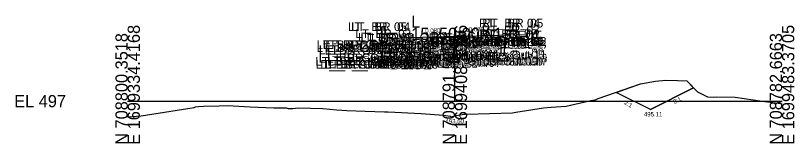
# Model space of a CAD drawing. Extents: x -63 to 1153, y -24 to 9522.
# Drawn here: x -25.7 to 152.8, y 6490.3 to 6519.6 of the extents above; entities that cross this region are included whole.
import ezdxf

# ---------------------------------------------------------------- set-up
doc = ezdxf.new("R2010")
doc.units = 0
for name, color, linetype in [('Default', 7, 'Continuous'), ('Exist Cross Section Cell', 7, 'Continuous'), ('Exist XS Center Line Elevation Label', 7, 'Continuous'), ('Exist XS Ground Line', 7, 'Continuous'), ('Prop CMT Concrete Structures', 7, 'Continuous'), ('Prop CMT DNC', 7, 'Continuous'), ('Prop CMT Slope Grass', 7, 'Continuous'), ('Prop XS DDE Earthwork Shape', 7, 'Continuous'), ('Prop XS Ditch Standard Text', 7, 'Continuous'), ('Prop XS SE Text', 7, 'Continuous'), ('Prop XS Side Slope Text', 7, 'Continuous')]:
    doc.layers.add(name, color=color, linetype=linetype)

msp = doc.modelspace()

# ---------------------------------------------------------------- linework, layer by layer
at = {"layer": 'Exist Cross Section Cell'}
for p, q in [((75, 6500), (75, 6516.82)), ((0, 6500), (75, 6500)), ((75, 6500), (150, 6500))]:
    msp.add_line(p, q, dxfattribs=at)
at = {"layer": 'Exist XS Ground Line'}
msp.add_lwpolyline([(0, 6496.43), (3.08, 6496.65), (15.21, 6498.56), (15.58, 6498.72), (16.25, 6498.8), (17.36, 6498.84), (20.94, 6498.96), (22.89, 6498.97), (28.09, 6498.68), (33.49, 6498.49), (36.36, 6498.44), (36.76, 6498.34), (37.14, 6498.31), (37.56, 6498.31), (37.88, 6498.34), (39.09, 6498.44), (44.77, 6498.3), (47.95, 6497.99), (50.26, 6497.85), (54.47, 6497.68), (58.91, 6497.54), (59.26, 6497.55), (59.68, 6497.55), (67.29, 6497.2), (72.37, 6496.81), (74.03, 6496.54), (74.22, 6496.44), (75, 6496.6), (77.05, 6497.02), (77.36, 6497.05), (77.65, 6497.04), (88.23, 6497.32), (88.99, 6497.48), (95.31, 6498.49), (97.05, 6498.64), (100.48, 6498.86), (106.14, 6500.13), (107.09, 6500.27), (107.22, 6500.32), (107.82, 6500.57), (117.56, 6503.95), (121.02, 6504.55), (123.34, 6504.8), (126.05, 6504.72), (128.18, 6504.62), (130.6, 6502.1), (132.88, 6500.98), (134.19, 6500.92), (134.98, 6500.96), (139.26, 6500.88), (145.48, 6499.97), (149.76, 6499.46), (150, 6499.42)], dxfattribs=at)
at = {"layer": 'Prop CMT Concrete Structures'}
for points in [[(75, 6514.85), (65.04, 6514.55), (59.75, 6514.39), (59.74, 6514.64), (59.16, 6515.48), (58.99, 6517.06), (58.25, 6517.06), (58.25, 6512.85)], [(75, 6514.85), (85, 6515.15), (87.59, 6515.23), (87.6, 6515.48), (88.18, 6516.31), (88.35, 6517.89), (89.09, 6517.89), (89.09, 6513.77)], [(75, 6513.35), (75, 6514.85)], [(75, 6513.35), (75, 6514.85)], [(58.25, 6512.85), (65.04, 6513.05), (75, 6513.35)], [(62.21, 6512.97), (61.37, 6512.94), (60.54, 6512.92)], [(60.54, 6512.92), (60.54, 6512.27)], [(62.21, 6512.27), (62.21, 6512.97)], [(75, 6513.35), (74.17, 6513.33)], [(74.17, 6513.33), (74.17, 6512.68)], [(89.09, 6513.77), (85, 6513.65), (75, 6513.35)], [(75, 6513.35), (75.83, 6513.38)], [(75, 6508.85), (75, 6513.35)], [(75, 6508.85), (75, 6513.35)], [(75.83, 6513.38), (75.83, 6512.68)], [(85.13, 6513.65), (85.97, 6513.68), (86.8, 6513.7)], [(85.13, 6513.01), (85.13, 6513.65)], [(85.63, 6512.51), (85.13, 6513.01)], [(86.8, 6513.01), (86.3, 6512.51)], [(86.8, 6513.7), (86.8, 6513.01)], [(60.54, 6512.27), (61.04, 6511.77)], [(61.04, 6511.77), (61.04, 6509.86)], [(61.71, 6511.77), (62.21, 6512.27)], [(61.71, 6509.86), (61.71, 6511.77)], [(74.17, 6512.68), (74.67, 6512.18)], [(74.67, 6512.18), (74.67, 6510.27)], [(75.83, 6512.68), (75.33, 6512.18)], [(75.33, 6512.18), (75.33, 6510.27)], [(85.63, 6510.6), (85.63, 6512.51)], [(86.3, 6512.51), (86.3, 6510.6)], [(61.04, 6509.86), (60.29, 6509.11)], [(62.46, 6509.11), (61.71, 6509.86)], [(74.67, 6510.27), (73.92, 6509.52)], [(73.92, 6509.52), (73.92, 6508.85)], [(75.33, 6510.27), (76.08, 6509.52)], [(76.08, 6509.52), (76.08, 6508.85)], [(84.88, 6509.85), (85.63, 6510.6)], [(84.88, 6509.18), (84.88, 6509.85)], [(86.3, 6510.6), (87.05, 6509.85)], [(87.05, 6509.85), (87.05, 6509.18)], [(60.29, 6509.11), (60.29, 6508.44)], [(60.29, 6508.44), (61.37, 6508.44), (62.46, 6508.44)], [(62.46, 6508.44), (62.46, 6509.11)], [(73.92, 6508.85), (75, 6508.85)], [(76.08, 6508.85), (75, 6508.85)], [(87.05, 6509.18), (85.97, 6509.18), (84.88, 6509.18)]]:
    msp.add_lwpolyline(points, dxfattribs=at)
at = {"layer": 'Prop CMT Slope Grass'}
for q in [(129.69, 6503.04), (112, 6502.02)]:
    msp.add_line((119.83, 6498.11), q, dxfattribs=at)
at = {"layer": 'Prop XS DDE Earthwork Shape'}
msp.add_lwpolyline([(112, 6502.02), (117.56, 6503.95), (121.02, 6504.55), (123.34, 6504.8), (126.05, 6504.72), (128.18, 6504.62), (129.69, 6503.04), (119.83, 6498.11)], close=True, dxfattribs=at)

# ---------------------------------------------------------------- texts
at = {"layer": 'Default'}
msp.add_text('-', height=0.0001, dxfattribs=at).set_placement((0, 6500))
at = {"layer": 'Exist Cross Section Cell'}
for s, p in [('L', (65, 6516.82)), ('15+50.00 / 1', (65, 6514.02)), ('EL 497', (-26, 6498.6))]:
    msp.add_text(s, height=2.8, dxfattribs=at).set_placement(p)
for s, p in [('E 1699334.4168', (2.8, 6490)), ('E 1699408.8936', (77.8, 6490)), ('E 1699483.3705', (152.8, 6490)), ('N 708800.3518', (0, 6490)), ('N 708791.5091', (75, 6490)), ('N 708782.6663', (150, 6490))]:
    msp.add_text(s, height=2.8, rotation=90, dxfattribs=at).set_placement(p)
at = {"layer": 'Exist XS Center Line Elevation Label'}
msp.add_text('493.60', height=1, dxfattribs=at).set_placement((72.85, 6494.89))
at = {"layer": 'Prop CMT DNC'}
for s, p in [('RT_ BR_04', (80.54, 6516.89)), ('RT_ BR_05', (81.28, 6516.89)), ('LT_ BR_05', (50.49, 6516.06)), ('LT_ BR_04', (51.23, 6516.06)), ('LT_BR_03', (52.21, 6514.48)), ('RT_BR_02', (80.61, 6514.48)), ('RT_BR_03', (81.19, 6515.31)), ('LT_BR_02', (52.8, 6513.64)), ('LT_BR_01', (53.37, 6513.39)), ('LT_PV1_OEOT', (55.78, 6513.55)), ('RT_BR_Girder Out 14', (68.52, 6512.65)), ('RT_BR_Girder Out 01', (69.27, 6512.68)), ('PV1_PGL', (69.47, 6513.85)), ('RT_BR_Girder Out 02', (69.54, 6512.7)), ('RT_PV1_OEOT', (75.69, 6514.15)), ('RT_BR_07', (78.01, 6512.65)), ('RT_BR_01', (81.17, 6514.23)), ('RT_BR_06', (82.05, 6512.77)), ('LT_BR_Girder Out 02', (43.33, 6511.92)), ('LT_BR_Girder Out 03', (43.33, 6511.27)), ('LT_BR_Girder Out 04', (43.83, 6510.77)), ('LT_BR_Girder Out 01', (44.73, 6511.94)), ('LT_BR_Girder Out 12', (45.14, 6510.77)), ('LT_BR_Girder Out 14', (45.64, 6511.97)), ('LT_BR_Girder Out 13', (45.64, 6511.27)), ('LT_BR_06', (51.26, 6511.85)), ('LT_BR_Girder Mid 02', (57.35, 6512.33)), ('LT_BR_Girder Mid 03', (57.35, 6511.68)), ('LT_BR_Girder Mid 04', (57.85, 6511.18)), ('LT_BR_07', (58.09, 6512.05)), ('RT_BR_Girder Mid 04', (58.47, 6511.18)), ('RT_BR_Girder Mid 02', (58.97, 6512.38)), ('RT_BR_Girder Mid 03', (58.97, 6511.68)), ('RT_BR_Girder Out 13', (68.52, 6512.01)), ('RT_BR_Girder Out 12', (69.02, 6511.51)), ('RT_BR_Girder Out 04', (69.04, 6511.51)), ('RT_BR_Girder Out 03', (69.54, 6512.01)), ('BR_PGL', (69.83, 6512.35)), ('LT_BR_Girder Mid 05', (57.85, 6509.27)), ('RT_BR_Girder Mid 05', (58.47, 6509.27)), ('RT_BR_Girder Out 05', (69.04, 6509.6)), ('RT_BR_Girder Out 11', (69.59, 6509.6)), ('LT_BR_Girder Out 06', (43.03, 6508.11)), ('LT_BR_Girder Out 07', (43.08, 6507.44)), ('LT_BR_Girder Out 05', (43.83, 6508.86)), ('LT_BR_Girder Out 08', (44.16, 6507.44)), ('LT_BR_Girder Out 09', (45.25, 6507.44)), ('LT_BR_Girder Out 11', (45.71, 6508.86)), ('LT_BR_Girder Out 10', (45.81, 6508.11)), ('LT_BR_Girder Mid 06', (57.05, 6508.52)), ('LT_BR_Girder Mid 07', (57.1, 6507.85)), ('RT_BR_Girder Mid 06', (59.17, 6508.52)), ('RT_BR_Girder Mid 07', (59.22, 6507.85)), ('BR_Girder Mid 08', (60.87, 6507.85)), ('RT_BR_Girder Out 09', (67.62, 6508.18)), ('RT_BR_Girder Out 10', (68.19, 6508.85)), ('RT_BR_Girder Out 08', (68.71, 6508.18)), ('RT_BR_Girder Out 06', (69.74, 6508.85)), ('RT_BR_Girder Out 07', (69.79, 6508.18))]:
    msp.add_text(s, height=2, dxfattribs=at).set_placement(p)
at = {"layer": 'Prop XS Ditch Standard Text'}
msp.add_text('495.11', height=1, dxfattribs=at).set_placement((118.34, 6496.49))
at = {"layer": 'Prop XS SE Text'}
for p in [(68.24, 6515.65), (78.22, 6515.95)]:
    msp.add_text('0.030', height=1, rotation=1.7184, dxfattribs=at).set_placement(p)
at = {"layer": 'Prop XS Side Slope Text'}
for rotation, p in [(26.5651, (125.33, 6499.31)), (329.9267, (113.7, 6499.39))]:
    msp.add_text('2:1', height=1, rotation=rotation, dxfattribs=at).set_placement(p)

doc.saveas('drawing.dxf')
